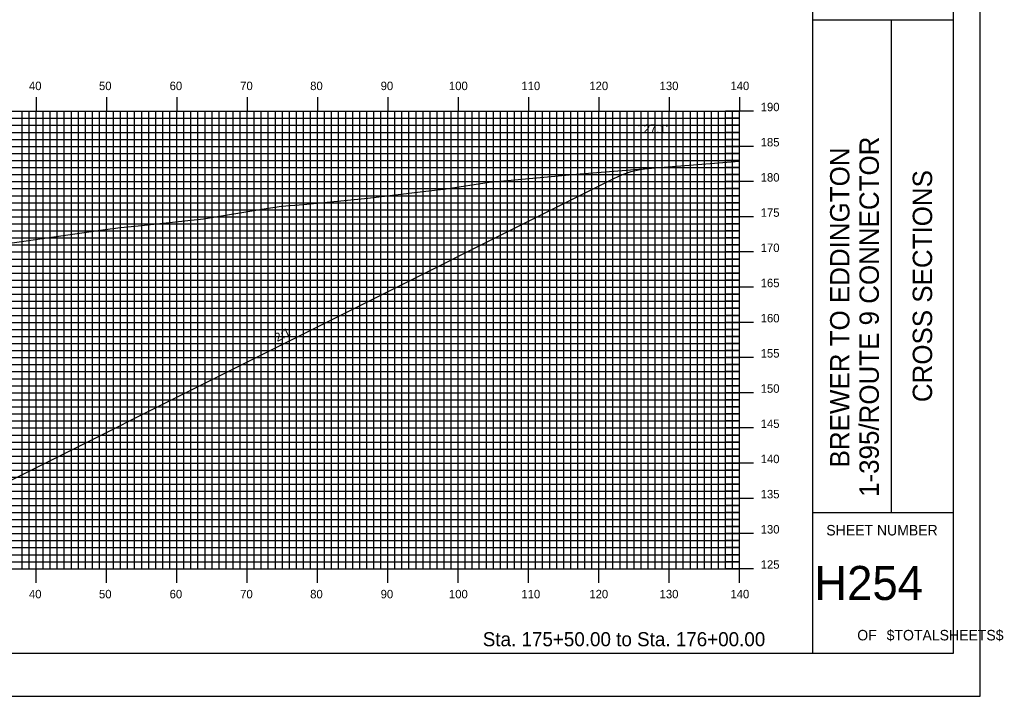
# Model space of a CAD drawing. Extents: x 1784221 to 1784564, y 442591 to 442811.
# Drawn here: x 1784424.7 to 1784564.5, y 442590.5 to 442686.7 of the extents above; entities that cross this region are included whole.
import ezdxf

# ---------------------------------------------------------------- set-up
doc = ezdxf.new("R2010")
doc.units = 0
for name, color, linetype in [('ANNOTATION', 7, 'Continuous'), ('BORDER', 7, 'Continuous'), ('D_Roadway_Centerline', 7, 'Continuous'), ('D_Roadway_SlopeLines', 7, 'Continuous'), ('D_Text_Standard', 7, 'Continuous'), ('H_V ANNOTATION', 7, 'Continuous'), ('MAJOR', 7, 'Continuous'), ('MINOR', 7, 'Continuous'), ('PLOT BOUNDARY', 7, 'Continuous'), ('S_Roadway_Centerline', 7, 'Continuous')]:
    doc.layers.add(name, color=color, linetype=linetype)

msp = doc.modelspace()

# ---------------------------------------------------------------- linework, layer by layer
at = {"layer": 'BORDER'}
for p, q in [((1784537.4, 442596.67), (1784537.4, 442806.67)), ((1784537.4, 442686.67), (1784557.4, 442686.67)), ((1784537.4, 442686.67), (1784557.4, 442686.67)), ((1784548.58, 442616.67), (1784548.58, 442686.67)), ((1784548.58, 442616.67), (1784548.58, 442686.67)), ((1784537.4, 442616.67), (1784557.4, 442616.67)), ((1784537.4, 442616.67), (1784557.4, 442616.67))]:
    msp.add_line(p, q, dxfattribs=at)
msp.add_lwpolyline([(1784237.4, 442596.67), (1784557.4, 442596.67), (1784557.4, 442806.67), (1784237.4, 442806.67)], close=True, dxfattribs=at)
at = {"layer": 'D_Roadway_Centerline'}
msp.add_lwpolyline([(1784298.69, 442641.6), (1784299.94, 442641.59), (1784301.19, 442641.41), (1784302.44, 442641.05), (1784303.69, 442640.51), (1784352.83, 442615.94), (1784356.83, 442616.94), (1784367, 442619.49), (1784375, 442619.81), (1784387, 442620.07), (1784399, 442620.33), (1784407, 442620.01), (1784416.27, 442617.7), (1784416.27, 442617.7), (1784509.11, 442664.11), (1784510.36, 442664.67), (1784511.61, 442665.1), (1784512.86, 442665.4), (1784514.11, 442665.56)], dxfattribs=at)
at = {"layer": 'D_Roadway_SlopeLines'}
msp.add_lwpolyline([(1784416.27, 442617.7), (1784509.11, 442664.11), (1784510.36, 442664.67), (1784511.61, 442665.1), (1784512.86, 442665.4), (1784514.11, 442665.56)], dxfattribs=at)
at = {"layer": 'MAJOR'}
for p, q in [((1784427, 442675.67), (1784427, 442673.67)), ((1784437, 442675.67), (1784437, 442673.67)), ((1784447, 442675.67), (1784447, 442673.67)), ((1784457, 442675.67), (1784457, 442673.67)), ((1784467, 442675.67), (1784467, 442673.67)), ((1784477, 442675.67), (1784477, 442673.67)), ((1784487, 442675.67), (1784487, 442673.67)), ((1784497, 442675.67), (1784497, 442673.67)), ((1784507, 442675.67), (1784507, 442673.67)), ((1784517, 442675.67), (1784517, 442673.67)), ((1784527, 442675.67), (1784527, 442673.67)), ((1784247, 442673.67), (1784527, 442673.67)), ((1784247, 442673.67), (1784527, 442673.67)), ((1784427, 442608.67), (1784427, 442673.67)), ((1784437, 442608.67), (1784437, 442673.67)), ((1784447, 442608.67), (1784447, 442673.67)), ((1784457, 442608.67), (1784457, 442673.67)), ((1784467, 442608.67), (1784467, 442673.67)), ((1784477, 442608.67), (1784477, 442673.67)), ((1784487, 442608.67), (1784487, 442673.67)), ((1784497, 442608.67), (1784497, 442673.67)), ((1784507, 442608.67), (1784507, 442673.67)), ((1784517, 442608.67), (1784517, 442673.67)), ((1784529, 442673.67), (1784525, 442673.67)), ((1784527, 442608.67), (1784527, 442673.67)), ((1784527, 442608.67), (1784527, 442673.67)), ((1784247, 442668.67), (1784527, 442668.67)), ((1784529, 442668.67), (1784525, 442668.67)), ((1784247, 442663.67), (1784527, 442663.67)), ((1784529, 442663.67), (1784525, 442663.67)), ((1784247, 442658.67), (1784527, 442658.67)), ((1784529, 442658.67), (1784525, 442658.67)), ((1784247, 442653.67), (1784527, 442653.67)), ((1784529, 442653.67), (1784525, 442653.67)), ((1784247, 442648.67), (1784527, 442648.67)), ((1784529, 442648.67), (1784525, 442648.67)), ((1784247, 442643.67), (1784527, 442643.67)), ((1784529, 442643.67), (1784525, 442643.67)), ((1784247, 442638.67), (1784527, 442638.67)), ((1784529, 442638.67), (1784525, 442638.67)), ((1784247, 442633.67), (1784527, 442633.67)), ((1784529, 442633.67), (1784525, 442633.67)), ((1784247, 442628.67), (1784527, 442628.67)), ((1784529, 442628.67), (1784525, 442628.67)), ((1784247, 442623.67), (1784527, 442623.67)), ((1784529, 442623.67), (1784525, 442623.67)), ((1784247, 442618.67), (1784527, 442618.67)), ((1784529, 442618.67), (1784525, 442618.67)), ((1784247, 442613.67), (1784527, 442613.67)), ((1784529, 442613.67), (1784525, 442613.67)), ((1784247, 442608.67), (1784527, 442608.67)), ((1784247, 442608.67), (1784527, 442608.67)), ((1784427, 442606.66), (1784427, 442608.67)), ((1784437, 442606.66), (1784437, 442608.67)), ((1784447, 442606.66), (1784447, 442608.67)), ((1784457, 442606.66), (1784457, 442608.67)), ((1784467, 442606.66), (1784467, 442608.67)), ((1784477, 442606.66), (1784477, 442608.67)), ((1784487, 442606.66), (1784487, 442608.67)), ((1784497, 442606.66), (1784497, 442608.67)), ((1784507, 442606.66), (1784507, 442608.67)), ((1784517, 442606.66), (1784517, 442608.67)), ((1784529, 442608.67), (1784525, 442608.67)), ((1784527, 442606.66), (1784527, 442608.67))]:
    msp.add_line(p, q, dxfattribs=at)
at = {"layer": 'MINOR'}
for p, q in [((1784425, 442608.67), (1784425, 442673.67)), ((1784426, 442608.67), (1784426, 442673.67)), ((1784428, 442608.67), (1784428, 442673.67)), ((1784429, 442608.67), (1784429, 442673.67)), ((1784430, 442608.67), (1784430, 442673.67)), ((1784431, 442608.67), (1784431, 442673.67)), ((1784432, 442608.67), (1784432, 442673.67)), ((1784433, 442608.67), (1784433, 442673.67)), ((1784434, 442608.67), (1784434, 442673.67)), ((1784435, 442608.67), (1784435, 442673.67)), ((1784436, 442608.67), (1784436, 442673.67)), ((1784438, 442608.67), (1784438, 442673.67)), ((1784439, 442608.67), (1784439, 442673.67)), ((1784440, 442608.67), (1784440, 442673.67)), ((1784441, 442608.67), (1784441, 442673.67)), ((1784442, 442608.67), (1784442, 442673.67)), ((1784443, 442608.67), (1784443, 442673.67)), ((1784444, 442608.67), (1784444, 442673.67)), ((1784445, 442608.67), (1784445, 442673.67)), ((1784446, 442608.67), (1784446, 442673.67)), ((1784448, 442608.67), (1784448, 442673.67)), ((1784449, 442608.67), (1784449, 442673.67)), ((1784450, 442608.67), (1784450, 442673.67)), ((1784451, 442608.67), (1784451, 442673.67)), ((1784452, 442608.67), (1784452, 442673.67)), ((1784453, 442608.67), (1784453, 442673.67)), ((1784454, 442608.67), (1784454, 442673.67)), ((1784455, 442608.67), (1784455, 442673.67)), ((1784456, 442608.67), (1784456, 442673.67)), ((1784458, 442608.67), (1784458, 442673.67)), ((1784459, 442608.67), (1784459, 442673.67)), ((1784460, 442608.67), (1784460, 442673.67)), ((1784461, 442608.67), (1784461, 442673.67)), ((1784462, 442608.67), (1784462, 442673.67)), ((1784463, 442608.67), (1784463, 442673.67)), ((1784464, 442608.67), (1784464, 442673.67)), ((1784465, 442608.67), (1784465, 442673.67)), ((1784466, 442608.67), (1784466, 442673.67)), ((1784468, 442608.67), (1784468, 442673.67)), ((1784469, 442608.67), (1784469, 442673.67)), ((1784470, 442608.67), (1784470, 442673.67)), ((1784471, 442608.67), (1784471, 442673.67)), ((1784472, 442608.67), (1784472, 442673.67)), ((1784473, 442608.67), (1784473, 442673.67)), ((1784474, 442608.67), (1784474, 442673.67)), ((1784475, 442608.67), (1784475, 442673.67)), ((1784476, 442608.67), (1784476, 442673.67)), ((1784478, 442608.67), (1784478, 442673.67)), ((1784479, 442608.67), (1784479, 442673.67)), ((1784480, 442608.67), (1784480, 442673.67)), ((1784481, 442608.67), (1784481, 442673.67)), ((1784482, 442608.67), (1784482, 442673.67)), ((1784483, 442608.67), (1784483, 442673.67)), ((1784484, 442608.67), (1784484, 442673.67)), ((1784485, 442608.67), (1784485, 442673.67)), ((1784486, 442608.67), (1784486, 442673.67)), ((1784488, 442608.67), (1784488, 442673.67)), ((1784489, 442608.67), (1784489, 442673.67)), ((1784490, 442608.67), (1784490, 442673.67)), ((1784491, 442608.67), (1784491, 442673.67)), ((1784492, 442608.67), (1784492, 442673.67)), ((1784493, 442608.67), (1784493, 442673.67)), ((1784494, 442608.67), (1784494, 442673.67)), ((1784495, 442608.67), (1784495, 442673.67)), ((1784496, 442608.67), (1784496, 442673.67)), ((1784498, 442608.67), (1784498, 442673.67)), ((1784499, 442608.67), (1784499, 442673.67)), ((1784500, 442608.67), (1784500, 442673.67)), ((1784501, 442608.67), (1784501, 442673.67)), ((1784502, 442608.67), (1784502, 442673.67)), ((1784503, 442608.67), (1784503, 442673.67)), ((1784504, 442608.67), (1784504, 442673.67)), ((1784505, 442608.67), (1784505, 442673.67)), ((1784506, 442608.67), (1784506, 442673.67)), ((1784508, 442608.67), (1784508, 442673.67)), ((1784509, 442608.67), (1784509, 442673.67)), ((1784510, 442608.67), (1784510, 442673.67)), ((1784511, 442608.67), (1784511, 442673.67)), ((1784512, 442608.67), (1784512, 442673.67)), ((1784513, 442608.67), (1784513, 442673.67)), ((1784514, 442608.67), (1784514, 442673.67)), ((1784515, 442608.67), (1784515, 442673.67)), ((1784516, 442608.67), (1784516, 442673.67)), ((1784518, 442608.67), (1784518, 442673.67)), ((1784519, 442608.67), (1784519, 442673.67)), ((1784520, 442608.67), (1784520, 442673.67)), ((1784521, 442608.67), (1784521, 442673.67)), ((1784522, 442608.67), (1784522, 442673.67)), ((1784523, 442608.67), (1784523, 442673.67)), ((1784524, 442608.67), (1784524, 442673.67)), ((1784525, 442608.67), (1784525, 442673.67)), ((1784526, 442608.67), (1784526, 442673.67)), ((1784247, 442672.67), (1784527, 442672.67)), ((1784527, 442672.67), (1784525, 442672.67)), ((1784247, 442671.67), (1784527, 442671.67)), ((1784247, 442670.67), (1784527, 442670.67)), ((1784527, 442671.67), (1784525, 442671.67)), ((1784527, 442670.67), (1784525, 442670.67)), ((1784247, 442669.67), (1784527, 442669.67)), ((1784527, 442669.67), (1784525, 442669.67)), ((1784247, 442667.67), (1784527, 442667.67)), ((1784247, 442666.67), (1784527, 442666.67)), ((1784527, 442667.67), (1784525, 442667.67)), ((1784527, 442666.67), (1784525, 442666.67)), ((1784247, 442665.67), (1784527, 442665.67)), ((1784527, 442665.67), (1784525, 442665.67)), ((1784247, 442664.67), (1784527, 442664.67)), ((1784527, 442664.67), (1784525, 442664.67)), ((1784247, 442662.67), (1784527, 442662.67)), ((1784527, 442662.67), (1784525, 442662.67)), ((1784247, 442661.67), (1784527, 442661.67)), ((1784527, 442661.67), (1784525, 442661.67)), ((1784247, 442660.67), (1784527, 442660.67)), ((1784247, 442659.67), (1784527, 442659.67)), ((1784527, 442660.67), (1784525, 442660.67)), ((1784527, 442659.67), (1784525, 442659.67)), ((1784247, 442657.67), (1784527, 442657.67)), ((1784247, 442656.67), (1784527, 442656.67)), ((1784527, 442657.67), (1784525, 442657.67)), ((1784527, 442656.67), (1784525, 442656.67)), ((1784247, 442655.67), (1784527, 442655.67)), ((1784527, 442655.67), (1784525, 442655.67)), ((1784247, 442654.67), (1784527, 442654.67)), ((1784527, 442654.67), (1784525, 442654.67)), ((1784247, 442652.67), (1784527, 442652.67)), ((1784527, 442652.67), (1784525, 442652.67)), ((1784247, 442651.67), (1784527, 442651.67)), ((1784527, 442651.67), (1784525, 442651.67)), ((1784247, 442650.67), (1784527, 442650.67)), ((1784247, 442649.67), (1784527, 442649.67)), ((1784527, 442650.67), (1784525, 442650.67)), ((1784527, 442649.67), (1784525, 442649.67)), ((1784247, 442647.67), (1784527, 442647.67)), ((1784527, 442647.67), (1784525, 442647.67)), ((1784247, 442646.67), (1784527, 442646.67)), ((1784247, 442645.67), (1784527, 442645.67)), ((1784527, 442646.67), (1784525, 442646.67)), ((1784527, 442645.67), (1784525, 442645.67)), ((1784247, 442644.67), (1784527, 442644.67)), ((1784527, 442644.67), (1784525, 442644.67)), ((1784247, 442642.67), (1784527, 442642.67)), ((1784527, 442642.67), (1784525, 442642.67)), ((1784247, 442641.67), (1784527, 442641.67)), ((1784527, 442641.67), (1784525, 442641.67)), ((1784247, 442640.67), (1784527, 442640.67)), ((1784527, 442640.67), (1784525, 442640.67)), ((1784247, 442639.67), (1784527, 442639.67)), ((1784527, 442639.67), (1784525, 442639.67)), ((1784247, 442637.67), (1784527, 442637.67)), ((1784527, 442637.67), (1784525, 442637.67)), ((1784247, 442636.67), (1784527, 442636.67)), ((1784247, 442635.67), (1784527, 442635.67)), ((1784527, 442636.67), (1784525, 442636.67)), ((1784527, 442635.67), (1784525, 442635.67)), ((1784247, 442634.67), (1784527, 442634.67)), ((1784527, 442634.67), (1784525, 442634.67)), ((1784247, 442632.67), (1784527, 442632.67)), ((1784247, 442631.67), (1784527, 442631.67)), ((1784527, 442632.67), (1784525, 442632.67)), ((1784527, 442631.67), (1784525, 442631.67)), ((1784247, 442630.67), (1784527, 442630.67)), ((1784527, 442630.67), (1784525, 442630.67)), ((1784247, 442629.67), (1784527, 442629.67)), ((1784527, 442629.67), (1784525, 442629.67)), ((1784247, 442627.67), (1784527, 442627.67)), ((1784527, 442627.67), (1784525, 442627.67)), ((1784247, 442626.67), (1784527, 442626.67)), ((1784527, 442626.67), (1784525, 442626.67)), ((1784247, 442625.67), (1784527, 442625.67)), ((1784247, 442624.67), (1784527, 442624.67)), ((1784527, 442625.67), (1784525, 442625.67)), ((1784527, 442624.67), (1784525, 442624.67)), ((1784247, 442622.67), (1784527, 442622.67)), ((1784247, 442621.67), (1784527, 442621.67)), ((1784527, 442622.67), (1784525, 442622.67)), ((1784527, 442621.67), (1784525, 442621.67)), ((1784247, 442620.67), (1784527, 442620.67)), ((1784527, 442620.67), (1784525, 442620.67)), ((1784247, 442619.67), (1784527, 442619.67)), ((1784527, 442619.67), (1784525, 442619.67)), ((1784247, 442617.67), (1784527, 442617.67)), ((1784527, 442617.67), (1784525, 442617.67)), ((1784247, 442616.67), (1784527, 442616.67)), ((1784527, 442616.67), (1784525, 442616.67)), ((1784247, 442615.67), (1784527, 442615.67)), ((1784527, 442615.67), (1784525, 442615.67)), ((1784247, 442614.67), (1784527, 442614.67)), ((1784527, 442614.67), (1784525, 442614.67)), ((1784247, 442612.67), (1784527, 442612.67)), ((1784527, 442612.67), (1784525, 442612.67)), ((1784247, 442611.67), (1784527, 442611.67)), ((1784247, 442610.67), (1784527, 442610.67)), ((1784527, 442611.67), (1784525, 442611.67)), ((1784527, 442610.67), (1784525, 442610.67)), ((1784247, 442609.67), (1784527, 442609.67)), ((1784527, 442609.67), (1784525, 442609.67))]:
    msp.add_line(p, q, dxfattribs=at)
at = {"layer": 'PLOT BOUNDARY'}
msp.add_lwpolyline([(1784221.21, 442590.55), (1784561.21, 442590.55), (1784561.21, 442810.55), (1784221.21, 442810.55)], close=True, dxfattribs=at)
at = {"layer": 'S_Roadway_Centerline'}
msp.add_lwpolyline([(1784417.59, 442654.11), (1784436.83, 442656.85), (1784439, 442657.17), (1784441.48, 442657.41), (1784450.79, 442658.39), (1784459.06, 442659.74), (1784461.87, 442660.17), (1784464.99, 442660.43), (1784474.13, 442661.33), (1784481.61, 442662.21), (1784485.28, 442662.66), (1784491.42, 442663.58), (1784504.33, 442664.79), (1784527, 442666.58)], dxfattribs=at)

# ---------------------------------------------------------------- texts
at = {"layer": 'ANNOTATION'}
msp.add_text('2:1', height=1.2, rotation=26.9015, dxfattribs=at).set_placement((1784461.28, 442640.89))
at = {"layer": 'BORDER'}
for s, p in [('1-395/ROUTE 9 CONNECTOR', (1784546.8, 442618.87)), ('BREWER TO EDDINGTON', (1784542.62, 442623.07)), ('CROSS SECTIONS', (1784554.37, 442632.34)), ('CROSS SECTIONS', (1784554.37, 442632.34))]:
    msp.add_text(s, height=2.7557, rotation=90, dxfattribs=at).set_placement(p)
for s, height, p in [('SHEET NUMBER', 1.4905, (1784539.33, 442613.4)), ('SHEET NUMBER', 1.4905, (1784539.33, 442613.4)), ('H254', 4.839, (1784537.61, 442604.23)), ('OF', 1.491, (1784543.73, 442598.49)), ('OF', 1.491, (1784543.73, 442598.49)), ('$TOTALSHEETS$', 1.4905, (1784547.91, 442598.49))]:
    msp.add_text(s, height=height, dxfattribs=at).set_placement(p)
at = {"layer": 'D_Text_Standard'}
msp.add_text("127.1'", height=1.2, dxfattribs=at).set_placement((1784512.48, 442670.59))
at = {"layer": 'H_V ANNOTATION'}
for s, height, p in [('40', 1.2, (1784425.97, 442676.67)), ('50', 1.2, (1784435.93, 442676.67)), ('60', 1.2, (1784445.97, 442676.67)), ('70', 1.2, (1784456, 442676.67)), ('80', 1.2, (1784465.95, 442676.67)), ('90', 1.2, (1784475.97, 442676.67)), ('100', 1.2, (1784485.68, 442676.67)), ('110', 1.2, (1784495.98, 442676.67)), ('120', 1.2, (1784505.64, 442676.67)), ('130', 1.2, (1784515.63, 442676.67)), ('140', 1.2, (1784525.7, 442676.67)), ('190', 1.2, (1784530, 442673.67)), ('185', 1.2, (1784530, 442668.67)), ('180', 1.2, (1784530, 442663.67)), ('175', 1.2, (1784530, 442658.67)), ('170', 1.2, (1784530, 442653.67)), ('165', 1.2, (1784530, 442648.67)), ('160', 1.2, (1784530, 442643.67)), ('155', 1.2, (1784530, 442638.67)), ('150', 1.2, (1784530, 442633.67)), ('145', 1.2, (1784530, 442628.67)), ('140', 1.2, (1784530, 442623.67)), ('135', 1.2, (1784530, 442618.67)), ('130', 1.2, (1784530, 442613.67)), ('125', 1.2, (1784530, 442608.67)), ('40', 1.2, (1784425.97, 442604.47)), ('50', 1.2, (1784435.93, 442604.47)), ('60', 1.2, (1784445.97, 442604.47)), ('70', 1.2, (1784456, 442604.47)), ('80', 1.2, (1784465.95, 442604.47)), ('90', 1.2, (1784475.97, 442604.47)), ('100', 1.2, (1784485.68, 442604.47)), ('110', 1.2, (1784495.98, 442604.47)), ('120', 1.2, (1784505.64, 442604.47)), ('130', 1.2, (1784515.63, 442604.47)), ('140', 1.2, (1784525.7, 442604.47)), ('Sta. 175+50.00 to Sta. 176+00.00', 2.0004, (1784490.49, 442597.66))]:
    msp.add_text(s, height=height, dxfattribs=at).set_placement(p)

doc.saveas('drawing.dxf')
